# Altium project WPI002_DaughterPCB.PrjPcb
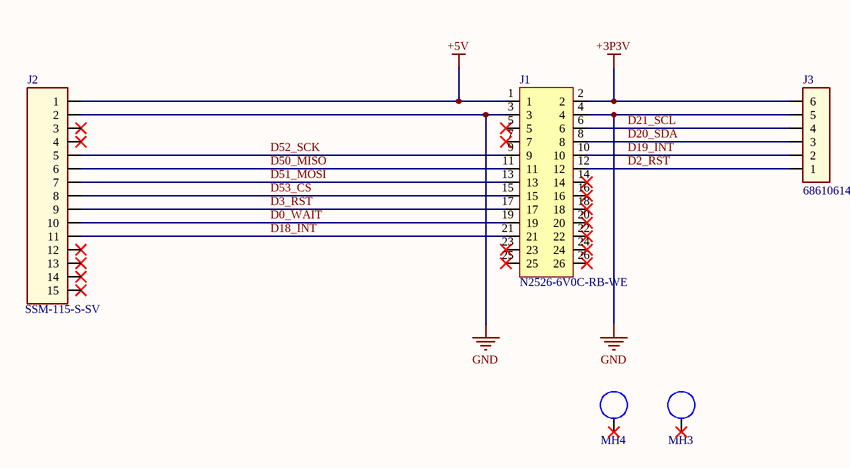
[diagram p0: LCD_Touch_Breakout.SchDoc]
1 sheet, 5 parts. Net scope: global (net labels, ports and power ports of the same name join across sheets).
Board file: WPI002_DaughterPCB.PcbDoc

## Sheet LCD_Touch_Breakout.SchDoc: LCD Adapter PCB
size Tabloid; Author: Y.Wong; CompanyName: Boston Engineering Corporation; Organization: Boston Engineering Corporation; Address1: 300 Bear Hill Road; Address2: Waltham, MA 02451; Address3: 781-466-8010; Revision: 1; SheetNumber: 1; SheetTotal: 1; Size: Tabloid; DrawnBy: Y.Wong; Engineer: M.Swanson; BarePcbNumber: 4390G01; AssyPcbNumber: 4391G01; DrawingNumber: 4392G01; ProjectCode: WPI002

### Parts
J1  N2526-6V0C-RB-WE  [3M\N2526-6V0C-RB-WE]
J2  SSM-115-S-SV  [SSM-115-S-SV]
J3  686106148922  [686106148922]
MH3  9774100151  [9774100151]  (value not drawn)
MH4  9774100151  [9774100151]  (value not drawn)

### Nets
+3P3V: J1.2 J3.6
+5V: J1.1 J2.1
GND: J1.3 J1.4 J2.2 J3.5
D0_WAIT: J1.19 J2.10
D2_RST: J1.12 J3.1
D3_RST: J1.17 J2.9
D18_INT: J1.21 J2.11
D19_INT: J1.10 J3.2
D20_SDA: J1.8 J3.3
D21_SCL: J1.6 J3.4
D50_MISO: J1.11 J2.6
D51_MOSI: J1.13 J2.7
D52_SCK: J1.9 J2.5
D53_CS: J1.15 J2.8

Not connected (* = marked no-connect by the designer): J1 5* 7* 14* 16* 18* 20* 22* 23* 24* 25* 26*; J2 3* 4* 12* 13* 14* 15*; MH3 1*; MH4 1*

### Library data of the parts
J1 = N2526-6V0C-RB-WE: CONN HEADER SMD 26POS 2.54MM; Manufacturer: 3M; Number of Contacts: 26; Gender: Male; Max Current Rating: 1.75A; Connector Type: Male Pin; Row Spacing: 0.1inch; Approvals: UL
J2 = SSM-115-S-SV: CONN RCPT 15POS 0.1 GOLD SMD; Manufacturer: Samtec; Number of Positions: 15; Pitch: 0.1inch; Gender: Female; Connector Type: Receptacle
J3 = 686106148922: CONN 1MM HORZ BOTTOM SMD 6POS; Manufacturer: Wurth Electronics; Actuator Material: Nylon,Polyamide; Voltage Rating: 100V; Current Rating: 1A; Number of Positions: 6; Gender: Receptacle; Wire/Cable Type: Straight; Pitch: 0.039inch
MH3 MH4 = 9774100151: RND STNDFF M2.5X0.45 STEEL 10MM; Manufacturer: Wurth Electronics; Manufacturer Part Number: 9774100151R; Plating: Tin; Threaded/Unthreaded: Threaded; Outside Diameter: 0.201inch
